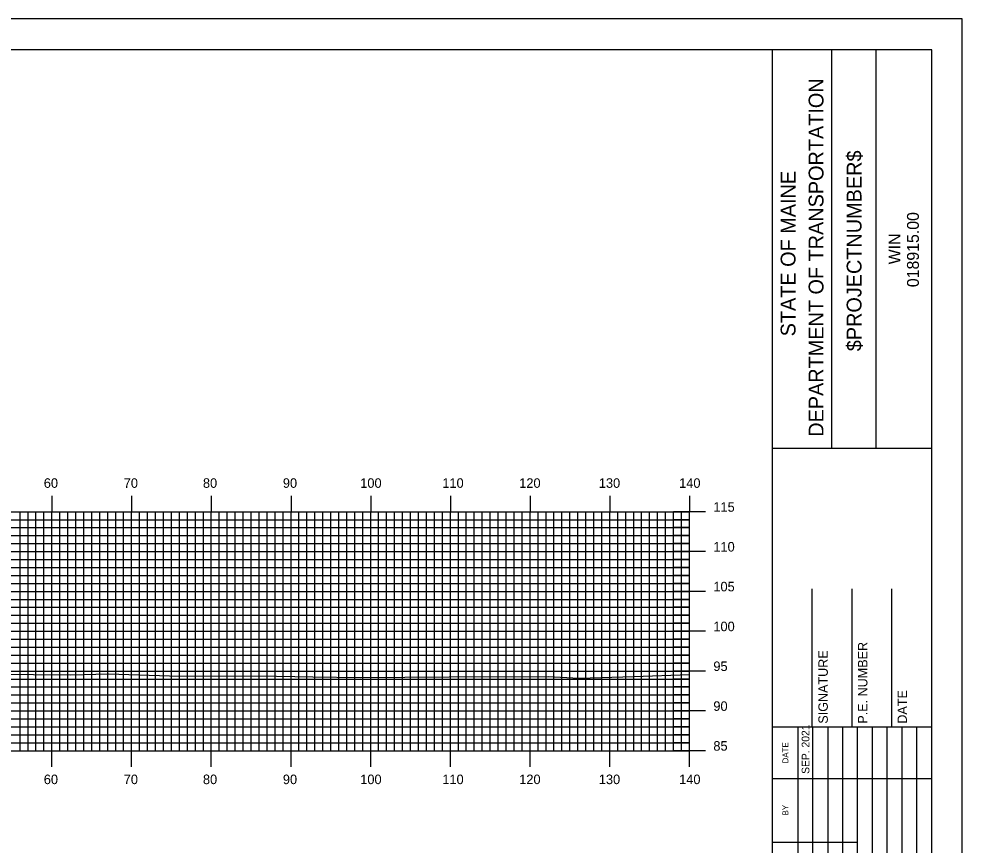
# Model space of a CAD drawing. Extents: x 1760610 to 1760954, y 442591 to 442811.
# Drawn here: x 1760832.1 to 1760950.4, y 442706.8 to 442810.5 of the extents above; entities that cross this region are included whole.
import ezdxf

# ---------------------------------------------------------------- set-up
doc = ezdxf.new("R2010")
doc.units = 0
for name, color, linetype in [('BORDER', 7, 'Continuous'), ('H_V ANNOTATION', 7, 'Continuous'), ('MAJOR', 7, 'Continuous'), ('MINOR', 7, 'Continuous'), ('PLOT BOUNDARY', 7, 'Continuous'), ('S_Roadway_Centerline', 7, 'Continuous')]:
    doc.layers.add(name, color=color, linetype=linetype)

msp = doc.modelspace()

# ---------------------------------------------------------------- linework, layer by layer
at = {"layer": 'BORDER'}
for p, q in [((1760926.61, 442596.67), (1760926.61, 442806.67)), ((1760934.07, 442756.66), (1760934.07, 442806.66)), ((1760939.66, 442756.66), (1760939.66, 442806.66)), ((1760926.62, 442756.65), (1760946.61, 442756.65)), ((1760931.61, 442721.67), (1760931.61, 442738.97)), ((1760936.61, 442721.67), (1760936.61, 442738.97)), ((1760941.61, 442721.67), (1760941.61, 442738.97)), ((1760926.61, 442721.67), (1760946.61, 442721.67))]:
    msp.add_line(p, q, dxfattribs=at)
msp.add_lwpolyline([(1760626.61, 442596.67), (1760946.61, 442596.67), (1760946.61, 442806.67), (1760626.61, 442806.67)], close=True, dxfattribs=at)
for points in [[(1760929.84, 442715.17), (1760929.84, 442721.67)], [(1760931.71, 442686.68), (1760931.71, 442721.67)], [(1760933.57, 442721.67), (1760933.57, 442686.68)], [(1760935.44, 442686.68), (1760935.44, 442721.67)], [(1760937.3, 442686.68), (1760937.3, 442721.67)], [(1760939.16, 442686.68), (1760939.16, 442721.67)], [(1760941.03, 442686.68), (1760941.03, 442721.67)], [(1760942.89, 442686.68), (1760942.89, 442721.67)], [(1760944.75, 442686.68), (1760944.75, 442721.67)], [(1760929.85, 442686.68), (1760929.85, 442720.26)], [(1760926.61, 442715.17), (1760946.61, 442715.17)], [(1760926.61, 442707.17), (1760929.85, 442707.17)], [(1760929.84, 442707.17), (1760937.3, 442707.17)]]:
    msp.add_lwpolyline(points, dxfattribs=at)
at = {"layer": 'MAJOR'}
for p, q in [((1760836.21, 442750.67), (1760836.21, 442748.67)), ((1760846.21, 442750.67), (1760846.21, 442748.67)), ((1760856.21, 442750.67), (1760856.21, 442748.67)), ((1760866.21, 442750.67), (1760866.21, 442748.67)), ((1760876.21, 442750.67), (1760876.21, 442748.67)), ((1760886.21, 442750.67), (1760886.21, 442748.67)), ((1760896.21, 442750.67), (1760896.21, 442748.67)), ((1760906.21, 442750.67), (1760906.21, 442748.67)), ((1760916.21, 442750.67), (1760916.21, 442748.67)), ((1760636.21, 442748.67), (1760916.21, 442748.67)), ((1760636.21, 442748.67), (1760916.21, 442748.67)), ((1760836.21, 442718.67), (1760836.21, 442748.67)), ((1760846.21, 442718.67), (1760846.21, 442748.67)), ((1760856.21, 442718.67), (1760856.21, 442748.67)), ((1760866.21, 442718.67), (1760866.21, 442748.67)), ((1760876.21, 442718.67), (1760876.21, 442748.67)), ((1760886.21, 442718.67), (1760886.21, 442748.67)), ((1760896.21, 442718.67), (1760896.21, 442748.67)), ((1760906.21, 442718.67), (1760906.21, 442748.67)), ((1760918.22, 442748.67), (1760914.21, 442748.67)), ((1760916.21, 442718.67), (1760916.21, 442748.67)), ((1760916.21, 442718.67), (1760916.21, 442748.67)), ((1760636.21, 442743.67), (1760916.21, 442743.67)), ((1760918.22, 442743.67), (1760914.21, 442743.67)), ((1760636.21, 442738.67), (1760916.21, 442738.67)), ((1760918.22, 442738.67), (1760914.21, 442738.67)), ((1760636.21, 442733.67), (1760916.21, 442733.67)), ((1760918.22, 442733.67), (1760914.21, 442733.67)), ((1760636.21, 442728.67), (1760916.21, 442728.67)), ((1760918.22, 442728.67), (1760914.21, 442728.67)), ((1760636.21, 442723.67), (1760916.21, 442723.67)), ((1760918.22, 442723.67), (1760914.21, 442723.67)), ((1760636.21, 442718.67), (1760916.21, 442718.67)), ((1760636.21, 442718.67), (1760916.21, 442718.67)), ((1760836.21, 442716.66), (1760836.21, 442718.67)), ((1760846.21, 442716.66), (1760846.21, 442718.67)), ((1760856.21, 442716.66), (1760856.21, 442718.67)), ((1760866.21, 442716.66), (1760866.21, 442718.67)), ((1760876.21, 442716.66), (1760876.21, 442718.67)), ((1760886.21, 442716.66), (1760886.21, 442718.67)), ((1760896.21, 442716.66), (1760896.21, 442718.67)), ((1760906.21, 442716.66), (1760906.21, 442718.67)), ((1760918.22, 442718.67), (1760914.21, 442718.67)), ((1760916.21, 442716.66), (1760916.21, 442718.67))]:
    msp.add_line(p, q, dxfattribs=at)
at = {"layer": 'MINOR'}
for p, q in [((1760832.21, 442718.67), (1760832.21, 442748.67)), ((1760833.21, 442718.67), (1760833.21, 442748.67)), ((1760834.21, 442718.67), (1760834.21, 442748.67)), ((1760835.21, 442718.67), (1760835.21, 442748.67)), ((1760837.21, 442718.67), (1760837.21, 442748.67)), ((1760838.21, 442718.67), (1760838.21, 442748.67)), ((1760839.21, 442718.67), (1760839.21, 442748.67)), ((1760840.21, 442718.67), (1760840.21, 442748.67)), ((1760841.21, 442718.67), (1760841.21, 442748.67)), ((1760842.21, 442718.67), (1760842.21, 442748.67)), ((1760843.21, 442718.67), (1760843.21, 442748.67)), ((1760844.21, 442718.67), (1760844.21, 442748.67)), ((1760845.21, 442718.67), (1760845.21, 442748.67)), ((1760847.21, 442718.67), (1760847.21, 442748.67)), ((1760848.21, 442718.67), (1760848.21, 442748.67)), ((1760849.21, 442718.67), (1760849.21, 442748.67)), ((1760850.21, 442718.67), (1760850.21, 442748.67)), ((1760851.21, 442718.67), (1760851.21, 442748.67)), ((1760852.21, 442718.67), (1760852.21, 442748.67)), ((1760853.21, 442718.67), (1760853.21, 442748.67)), ((1760854.21, 442718.67), (1760854.21, 442748.67)), ((1760855.21, 442718.67), (1760855.21, 442748.67)), ((1760857.21, 442718.67), (1760857.21, 442748.67)), ((1760858.21, 442718.67), (1760858.21, 442748.67)), ((1760859.21, 442718.67), (1760859.21, 442748.67)), ((1760860.21, 442718.67), (1760860.21, 442748.67)), ((1760861.21, 442718.67), (1760861.21, 442748.67)), ((1760862.21, 442718.67), (1760862.21, 442748.67)), ((1760863.21, 442718.67), (1760863.21, 442748.67)), ((1760864.21, 442718.67), (1760864.21, 442748.67)), ((1760865.21, 442718.67), (1760865.21, 442748.67)), ((1760867.21, 442718.67), (1760867.21, 442748.67)), ((1760868.21, 442718.67), (1760868.21, 442748.67)), ((1760869.21, 442718.67), (1760869.21, 442748.67)), ((1760870.21, 442718.67), (1760870.21, 442748.67)), ((1760871.21, 442718.67), (1760871.21, 442748.67)), ((1760872.21, 442718.67), (1760872.21, 442748.67)), ((1760873.21, 442718.67), (1760873.21, 442748.67)), ((1760874.21, 442718.67), (1760874.21, 442748.67)), ((1760875.21, 442718.67), (1760875.21, 442748.67)), ((1760877.21, 442718.67), (1760877.21, 442748.67)), ((1760878.21, 442718.67), (1760878.21, 442748.67)), ((1760879.21, 442718.67), (1760879.21, 442748.67)), ((1760880.21, 442718.67), (1760880.21, 442748.67)), ((1760881.21, 442718.67), (1760881.21, 442748.67)), ((1760882.21, 442718.67), (1760882.21, 442748.67)), ((1760883.21, 442718.67), (1760883.21, 442748.67)), ((1760884.21, 442718.67), (1760884.21, 442748.67)), ((1760885.21, 442718.67), (1760885.21, 442748.67)), ((1760887.21, 442718.67), (1760887.21, 442748.67)), ((1760888.21, 442718.67), (1760888.21, 442748.67)), ((1760889.21, 442718.67), (1760889.21, 442748.67)), ((1760890.21, 442718.67), (1760890.21, 442748.67)), ((1760891.21, 442718.67), (1760891.21, 442748.67)), ((1760892.21, 442718.67), (1760892.21, 442748.67)), ((1760893.21, 442718.67), (1760893.21, 442748.67)), ((1760894.21, 442718.67), (1760894.21, 442748.67)), ((1760895.21, 442718.67), (1760895.21, 442748.67)), ((1760897.21, 442718.67), (1760897.21, 442748.67)), ((1760898.21, 442718.67), (1760898.21, 442748.67)), ((1760899.21, 442718.67), (1760899.21, 442748.67)), ((1760900.21, 442718.67), (1760900.21, 442748.67)), ((1760901.21, 442718.67), (1760901.21, 442748.67)), ((1760902.21, 442718.67), (1760902.21, 442748.67)), ((1760903.21, 442718.67), (1760903.21, 442748.67)), ((1760904.21, 442718.67), (1760904.21, 442748.67)), ((1760905.21, 442718.67), (1760905.21, 442748.67)), ((1760907.21, 442718.67), (1760907.21, 442748.67)), ((1760908.21, 442718.67), (1760908.21, 442748.67)), ((1760909.21, 442718.67), (1760909.21, 442748.67)), ((1760910.21, 442718.67), (1760910.21, 442748.67)), ((1760911.21, 442718.67), (1760911.21, 442748.67)), ((1760912.21, 442718.67), (1760912.21, 442748.67)), ((1760913.21, 442718.67), (1760913.21, 442748.67)), ((1760914.21, 442718.67), (1760914.21, 442748.67)), ((1760915.21, 442718.67), (1760915.21, 442748.67)), ((1760636.21, 442747.67), (1760916.21, 442747.67)), ((1760916.21, 442747.67), (1760914.21, 442747.67)), ((1760636.21, 442746.67), (1760916.21, 442746.67)), ((1760916.21, 442746.67), (1760914.21, 442746.67)), ((1760636.21, 442745.67), (1760916.21, 442745.67)), ((1760916.21, 442745.67), (1760914.21, 442745.67)), ((1760636.21, 442744.67), (1760916.21, 442744.67)), ((1760916.21, 442744.67), (1760914.21, 442744.67)), ((1760636.21, 442742.67), (1760916.21, 442742.67)), ((1760916.21, 442742.67), (1760914.21, 442742.67)), ((1760636.21, 442741.67), (1760916.21, 442741.67)), ((1760916.21, 442741.67), (1760914.21, 442741.67)), ((1760636.21, 442740.67), (1760916.21, 442740.67)), ((1760916.21, 442740.67), (1760914.21, 442740.67)), ((1760636.21, 442739.67), (1760916.21, 442739.67)), ((1760916.21, 442739.67), (1760914.21, 442739.67)), ((1760636.21, 442737.67), (1760916.21, 442737.67)), ((1760636.21, 442736.67), (1760916.21, 442736.67)), ((1760916.21, 442737.67), (1760914.21, 442737.67)), ((1760916.21, 442736.67), (1760914.21, 442736.67)), ((1760636.21, 442735.67), (1760916.21, 442735.67)), ((1760916.21, 442735.67), (1760914.21, 442735.67)), ((1760636.21, 442734.67), (1760916.21, 442734.67)), ((1760916.21, 442734.67), (1760914.21, 442734.67)), ((1760636.21, 442732.67), (1760916.21, 442732.67)), ((1760916.21, 442732.67), (1760914.21, 442732.67)), ((1760636.21, 442731.67), (1760916.21, 442731.67)), ((1760916.21, 442731.67), (1760914.21, 442731.67)), ((1760636.21, 442730.67), (1760916.21, 442730.67)), ((1760636.21, 442729.67), (1760916.21, 442729.67)), ((1760916.21, 442730.67), (1760914.21, 442730.67)), ((1760916.21, 442729.67), (1760914.21, 442729.67)), ((1760636.21, 442727.67), (1760916.21, 442727.67)), ((1760916.21, 442727.67), (1760914.21, 442727.67)), ((1760636.21, 442726.67), (1760916.21, 442726.67)), ((1760916.21, 442726.67), (1760914.21, 442726.67)), ((1760636.21, 442725.67), (1760916.21, 442725.67)), ((1760916.21, 442725.67), (1760914.21, 442725.67)), ((1760636.21, 442724.67), (1760916.21, 442724.67)), ((1760916.21, 442724.67), (1760914.21, 442724.67)), ((1760636.21, 442722.67), (1760916.21, 442722.67)), ((1760916.21, 442722.67), (1760914.21, 442722.67)), ((1760636.21, 442721.67), (1760916.21, 442721.67)), ((1760916.21, 442721.67), (1760914.21, 442721.67)), ((1760636.21, 442720.67), (1760916.21, 442720.67)), ((1760916.21, 442720.67), (1760914.21, 442720.67)), ((1760636.21, 442719.67), (1760916.21, 442719.67)), ((1760916.21, 442719.67), (1760914.21, 442719.67))]:
    msp.add_line(p, q, dxfattribs=at)
at = {"layer": 'PLOT BOUNDARY'}
msp.add_lwpolyline([(1760610.43, 442590.55), (1760950.43, 442590.55), (1760950.43, 442810.55), (1760610.43, 442810.55)], close=True, dxfattribs=at)
at = {"layer": 'S_Roadway_Centerline'}
msp.add_lwpolyline([(1760828.99, 442728.28), (1760833.91, 442728.23), (1760838.53, 442728.21), (1760843.32, 442728.33), (1760852.25, 442728.03), (1760862.12, 442728.07), (1760868.94, 442727.95), (1760874.95, 442727.84), (1760886.04, 442727.96), (1760898.46, 442727.99), (1760902.36, 442727.79), (1760909.25, 442728), (1760916.21, 442728.25)], dxfattribs=at)

# ---------------------------------------------------------------- texts
at = {"layer": 'BORDER'}
for s, height, p in [('DEPARTMENT OF TRANSPORTATION', 1.8635, (1760933.03, 442758.08)), ('$PROJECTNUMBER$', 1.8635, (1760937.8, 442768.82)), ('STATE OF MAINE', 1.8635, (1760929.52, 442770.69)), ('018915.00', 1.491, (1760945, 442776.86)), ('WIN', 1.491, (1760942.69, 442779.73)), ('P.E. NUMBER', 1.1811, (1760938.54, 442722.06)), ('SIGNATURE', 1.181, (1760933.57, 442722.06)), ('DATE', 1.181, (1760943.5, 442722.06)), ('SEP. 2021', 0.969, (1760931.26, 442715.76)), ('DATE', 0.743, (1760928.62, 442717.08)), ('BY', 0.743, (1760928.62, 442710.54))]:
    msp.add_text(s, height=height, rotation=90, dxfattribs=at).set_placement(p)
at = {"layer": 'H_V ANNOTATION'}
for s, p in [('60', (1760835.19, 442751.67)), ('70', (1760845.22, 442751.67)), ('80', (1760855.16, 442751.67)), ('90', (1760865.19, 442751.67)), ('100', (1760874.9, 442751.67)), ('110', (1760885.2, 442751.67)), ('120', (1760894.85, 442751.67)), ('130', (1760904.84, 442751.67)), ('140', (1760914.92, 442751.67)), ('115', (1760919.21, 442748.67)), ('110', (1760919.21, 442743.67)), ('105', (1760919.21, 442738.67)), ('100', (1760919.21, 442733.67)), ('95', (1760919.21, 442728.67)), ('90', (1760919.21, 442723.67)), ('85', (1760919.21, 442718.67)), ('60', (1760835.19, 442714.47)), ('70', (1760845.22, 442714.47)), ('80', (1760855.16, 442714.47)), ('90', (1760865.19, 442714.47)), ('100', (1760874.9, 442714.47)), ('110', (1760885.2, 442714.47)), ('120', (1760894.85, 442714.47)), ('130', (1760904.84, 442714.47)), ('140', (1760914.92, 442714.47))]:
    msp.add_text(s, height=1.2, dxfattribs=at).set_placement(p)

doc.saveas('drawing.dxf')
